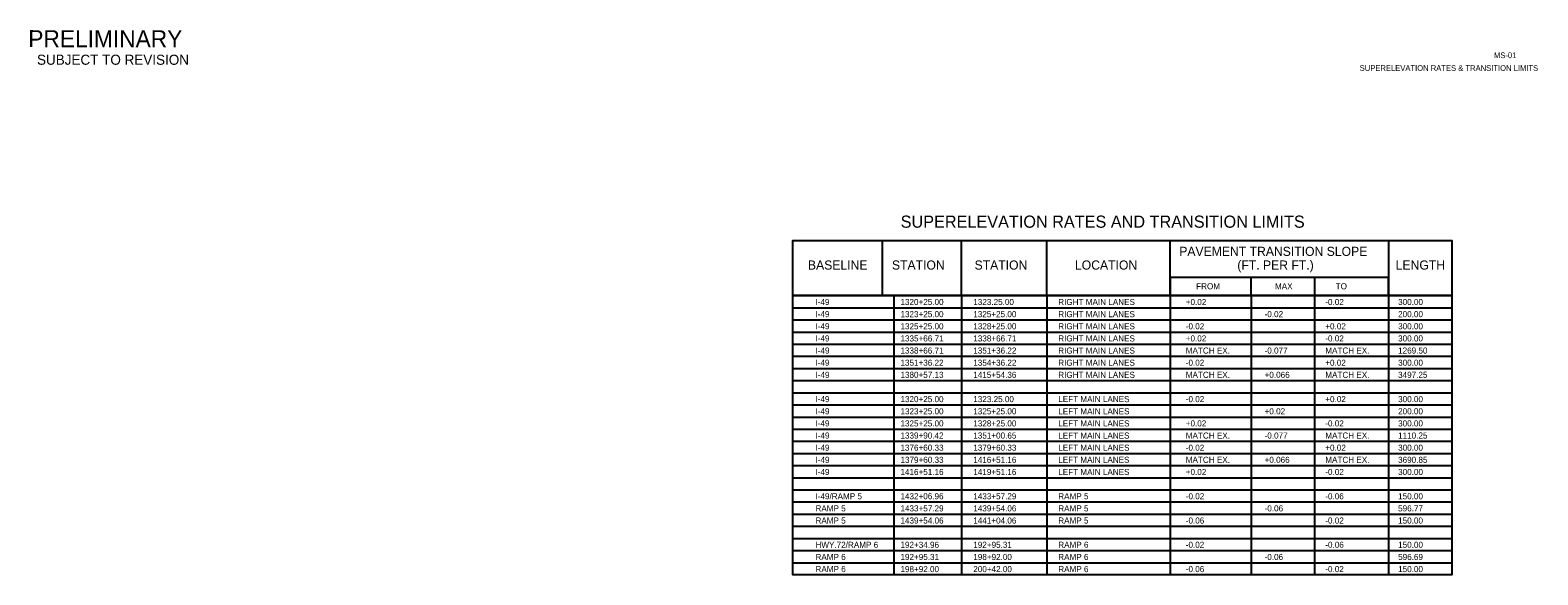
# Model space of a CAD drawing. Extents: x 1226579 to 1228132, y 151768 to 152328.
import ezdxf

# ---------------------------------------------------------------- set-up
doc = ezdxf.new("R2010")
doc.units = 0
for name, color, linetype in [('R_Border', 7, 'Continuous'), ('R_Border Notes', 7, 'Continuous'), ('R_Border Prem', 7, 'Continuous')]:
    doc.layers.add(name, color=color, linetype=linetype)

msp = doc.modelspace()

# ---------------------------------------------------------------- linework, layer by layer
at = {"layer": 'R_Border Notes'}
for p, q in [((1227456.8, 152055), (1227456.8, 152111.9)), ((1227538.1, 152055), (1227538.1, 152111.9)), ((1227625.9, 152055), (1227625.9, 152111.9)), ((1227753.1, 152055), (1227753.1, 152111.9)), ((1227977.8, 152111.9), (1227977.8, 151767.5)), ((1227836.6, 152055), (1227836.6, 152073.6)), ((1227901.8, 152073.6), (1227901.8, 151767.5)), ((1227387.8, 152055), (1228043, 152055)), ((1227468.5, 152055), (1227468.5, 151767.5)), ((1227538.1, 152055), (1227538.1, 151767.5)), ((1227625.9, 152055), (1227625.9, 151767.5)), ((1227753.1, 152055), (1227753.1, 151767.5)), ((1227836.6, 152055), (1227836.6, 151767.5)), ((1227364.5, 152042.5), (1228043, 152042.5)), ((1227364.5, 152030), (1228043, 152030)), ((1227364.5, 152017.5), (1228043, 152017.5)), ((1227364.5, 152005), (1228043, 152005)), ((1227364.5, 151992.5), (1228043, 151992.5)), ((1227364.5, 151980), (1228043, 151980)), ((1227364.5, 151967.5), (1228043, 151967.5)), ((1227364.5, 151955), (1228043, 151955)), ((1227364.5, 151942.5), (1228043, 151942.5)), ((1227364.5, 151930), (1228043, 151930)), ((1227364.5, 151917.5), (1228043, 151917.5)), ((1227364.5, 151905), (1228043, 151905)), ((1227364.5, 151892.5), (1228043, 151892.5)), ((1227364.5, 151880), (1228043, 151880)), ((1227364.5, 151867.5), (1228043, 151867.5)), ((1227364.5, 151855), (1228043, 151855)), ((1227364.5, 151842.5), (1228043, 151842.5)), ((1227364.5, 151830), (1228043, 151830)), ((1227364.5, 151817.5), (1228043, 151817.5)), ((1227364.5, 151805), (1228043, 151805)), ((1227364.5, 151792.5), (1228043, 151792.5)), ((1227364.5, 151780), (1228043, 151780))]:
    msp.add_line(p, q, dxfattribs=at)
for points in [[(1228043, 152055), (1227364.5, 152055), (1227364.5, 152111.9), (1228043, 152111.9)], [(1227753.1, 152055), (1227977.8, 152055), (1227977.8, 152073.6), (1227753.1, 152073.6)], [(1227364.5, 152055), (1228043, 152055), (1228043, 151767.5), (1227364.5, 151767.5)]]:
    msp.add_lwpolyline(points, close=True, dxfattribs=at)

# ---------------------------------------------------------------- texts
at = {"layer": 'R_Border'}
for s, height, p in [('MS-01', 5.86, (1228086.5, 152299.5)), ('SUPERELEVATION RATES & TRANSITION LIMITS', 5.862, (1227948.2, 152286.4))]:
    msp.add_text(s, height=height, dxfattribs=at).set_placement(p)
at = {"layer": 'R_Border Notes'}
for s, height, p in [('SUPERELEVATION RATES AND TRANSITION LIMITS', 12.5, (1227475.5, 152124.9)), ('PAVEMENT TRANSITION SLOPE', 9.375, (1227762.4, 152095.9)), ('BASELINE', 9.38, (1227380, 152081.8)), ('STATION', 9.38, (1227466.5, 152081.8)), ('STATION', 9.38, (1227551.6, 152081.8)), ('LOCATION', 9.38, (1227655, 152081.8)), ('(FT. PER FT.)', 9.375, (1227822.2, 152081.8)), ('LENGTH', 9.38, (1227985.3, 152081.8)), ('FROM', 6.25, (1227779.8, 152061.5)), ('MAX', 6.25, (1227861, 152061.5)), ('TO', 6.25, (1227923.5, 152061.5)), ('I-49', 6.25, (1227387.8, 152045.3)), ('I-49', 6.25, (1227387.8, 152032.8)), ('1320+25.00', 6.25, (1227475.3, 152045.3)), ('1323+25.00', 6.25, (1227475.3, 152032.8)), ('1323.25.00', 6.25, (1227550.3, 152045.3)), ('1325+25.00', 6.25, (1227550.3, 152032.8)), ('RIGHT MAIN LANES', 6.25, (1227637.8, 152045.3)), ('RIGHT MAIN LANES', 6.25, (1227637.8, 152032.8)), ('+0.02', 6.25, (1227769.1, 152045.3)), ('-0.02', 6.25, (1227850.3, 152032.8)), ('-0.02', 6.25, (1227912.8, 152045.3)), ('300.00', 6.25, (1227987.8, 152045.3)), ('200.00', 6.25, (1227987.8, 152032.8)), ('I-49', 6.25, (1227387.8, 152020.3)), ('1325+25.00', 6.25, (1227475.3, 152020.3)), ('1328+25.00', 6.25, (1227550.3, 152020.3)), ('RIGHT MAIN LANES', 6.25, (1227637.8, 152020.3)), ('-0.02', 6.25, (1227769.1, 152020.3)), ('+0.02', 6.25, (1227912.8, 152020.3)), ('300.00', 6.25, (1227987.8, 152020.3)), ('I-49', 6.25, (1227387.8, 152007.8)), ('1335+66.71', 6.25, (1227475.3, 152007.8)), ('1338+66.71', 6.25, (1227550.3, 152007.8)), ('RIGHT MAIN LANES', 6.25, (1227637.8, 152007.8)), ('+0.02', 6.25, (1227769.1, 152007.8)), ('-0.02', 6.25, (1227912.8, 152007.8)), ('300.00', 6.25, (1227987.8, 152007.8)), ('I-49', 6.25, (1227387.8, 151995.3)), ('1338+66.71', 6.25, (1227475.3, 151995.3)), ('1351+36.22', 6.25, (1227550.3, 151995.3)), ('RIGHT MAIN LANES', 6.25, (1227637.8, 151995.3)), ('MATCH EX.', 6.25, (1227769.1, 151995.3)), ('-0.077', 6.25, (1227850.3, 151995.3)), ('MATCH EX.', 6.25, (1227912.8, 151995.3)), ('1269.50', 6.25, (1227987.8, 151995.3)), ('I-49', 6.25, (1227387.8, 151982.8)), ('I-49', 6.25, (1227387.8, 151970.3)), ('1351+36.22', 6.25, (1227475.3, 151982.8)), ('1380+57.13', 6.25, (1227475.3, 151970.3)), ('1354+36.22', 6.25, (1227550.3, 151982.8)), ('1415+54.36', 6.25, (1227550.3, 151970.3)), ('RIGHT MAIN LANES', 6.25, (1227637.8, 151982.8)), ('RIGHT MAIN LANES', 6.25, (1227637.8, 151970.3)), ('-0.02', 6.25, (1227769.1, 151982.8)), ('MATCH EX.', 6.25, (1227769.1, 151970.3)), ('+0.066', 6.25, (1227850.3, 151970.3)), ('+0.02', 6.25, (1227912.8, 151982.8)), ('MATCH EX.', 6.25, (1227912.8, 151970.3)), ('300.00', 6.25, (1227987.8, 151982.8)), ('3497.25', 6.25, (1227987.8, 151970.3)), ('I-49', 6.25, (1227387.8, 151945.3)), ('1320+25.00', 6.25, (1227475.3, 151945.3)), ('1323.25.00', 6.25, (1227550.3, 151945.3)), ('LEFT MAIN LANES', 6.25, (1227637.8, 151945.3)), ('-0.02', 6.25, (1227769.1, 151945.3)), ('+0.02', 6.25, (1227912.8, 151945.3)), ('300.00', 6.25, (1227987.8, 151945.3)), ('I-49', 6.25, (1227387.8, 151932.8)), ('1323+25.00', 6.25, (1227475.3, 151932.8)), ('1325+25.00', 6.25, (1227550.3, 151932.8)), ('LEFT MAIN LANES', 6.25, (1227637.8, 151932.8)), ('+0.02', 6.25, (1227850.3, 151932.8)), ('200.00', 6.25, (1227987.8, 151932.8)), ('I-49', 6.25, (1227387.8, 151920.3)), ('I-49', 6.25, (1227387.8, 151907.8)), ('1325+25.00', 6.25, (1227475.3, 151920.3)), ('1339+90.42', 6.25, (1227475.3, 151907.8)), ('1328+25.00', 6.25, (1227550.3, 151920.3)), ('1351+00.65', 6.25, (1227550.3, 151907.8)), ('LEFT MAIN LANES', 6.25, (1227637.8, 151920.3)), ('LEFT MAIN LANES', 6.25, (1227637.8, 151907.8)), ('+0.02', 6.25, (1227769.1, 151920.3)), ('MATCH EX.', 6.25, (1227769.1, 151907.8)), ('-0.077', 6.25, (1227850.3, 151907.8)), ('-0.02', 6.25, (1227912.8, 151920.3)), ('MATCH EX.', 6.25, (1227912.8, 151907.8)), ('300.00', 6.25, (1227987.8, 151920.3)), ('1110.25', 6.25, (1227987.8, 151907.8)), ('I-49', 6.25, (1227387.8, 151895.3)), ('1376+60.33', 6.25, (1227475.3, 151895.3)), ('1379+60.33', 6.25, (1227550.3, 151895.3)), ('LEFT MAIN LANES', 6.25, (1227637.8, 151895.3)), ('-0.02', 6.25, (1227769.1, 151895.3)), ('+0.02', 6.25, (1227912.8, 151895.3)), ('300.00', 6.25, (1227987.8, 151895.3)), ('I-49', 6.25, (1227387.8, 151882.8)), ('1379+60.33', 6.25, (1227475.3, 151882.8)), ('1416+51.16', 6.25, (1227550.3, 151882.8)), ('LEFT MAIN LANES', 6.25, (1227637.8, 151882.8)), ('MATCH EX.', 6.25, (1227769.1, 151882.8)), ('+0.066', 6.25, (1227850.3, 151882.8)), ('MATCH EX.', 6.25, (1227912.8, 151882.8)), ('3690.85', 6.25, (1227987.8, 151882.8)), ('I-49', 6.25, (1227387.8, 151870.3)), ('1416+51.16', 6.25, (1227475.3, 151870.3)), ('1419+51.16', 6.25, (1227550.3, 151870.3)), ('LEFT MAIN LANES', 6.25, (1227637.8, 151870.3)), ('+0.02', 6.25, (1227769.1, 151870.3)), ('-0.02', 6.25, (1227912.8, 151870.3)), ('300.00', 6.25, (1227987.8, 151870.3)), ('I-49/RAMP 5', 6.25, (1227387.8, 151845.3)), ('1432+06.96', 6.25, (1227475.3, 151845.3)), ('1433+57.29', 6.25, (1227550.3, 151845.3)), ('RAMP 5', 6.25, (1227637.8, 151845.3)), ('-0.02', 6.25, (1227769.1, 151845.3)), ('-0.06', 6.25, (1227912.8, 151845.3)), ('150.00', 6.25, (1227987.8, 151845.3)), ('RAMP 5', 6.25, (1227387.8, 151832.8)), ('1433+57.29', 6.25, (1227475.3, 151832.8)), ('1439+54.06', 6.25, (1227550.3, 151832.8)), ('RAMP 5', 6.25, (1227637.8, 151832.8)), ('-0.06', 6.25, (1227850.3, 151832.8)), ('596.77', 6.25, (1227987.8, 151832.8)), ('RAMP 5', 6.25, (1227387.8, 151820.3)), ('1439+54.06', 6.25, (1227475.3, 151820.3)), ('1441+04.06', 6.25, (1227550.3, 151820.3)), ('RAMP 5', 6.25, (1227637.8, 151820.3)), ('-0.06', 6.25, (1227769.1, 151820.3)), ('-0.02', 6.25, (1227912.8, 151820.3)), ('150.00', 6.25, (1227987.8, 151820.3)), ('HWY.72/RAMP 6', 6.25, (1227387.8, 151795.3)), ('RAMP 6', 6.25, (1227387.8, 151782.8)), ('192+34.96', 6.25, (1227475.3, 151795.3)), ('192+95.31', 6.25, (1227475.3, 151782.8)), ('192+95.31', 6.25, (1227550.3, 151795.3)), ('198+92.00', 6.25, (1227550.3, 151782.8)), ('RAMP 6', 6.25, (1227637.8, 151795.3)), ('RAMP 6', 6.25, (1227637.8, 151782.8)), ('-0.02', 6.25, (1227769.1, 151795.3)), ('-0.06', 6.25, (1227850.3, 151782.8)), ('-0.06', 6.25, (1227912.8, 151795.3)), ('596.69', 6.25, (1227987.8, 151782.8)), ('150.00', 6.25, (1227987.8, 151795.3)), ('RAMP 6', 6.25, (1227387.8, 151770.3)), ('198+92.00', 6.25, (1227475.3, 151770.3)), ('200+42.00', 6.25, (1227550.3, 151770.3)), ('RAMP 6', 6.25, (1227637.8, 151770.3)), ('-0.06', 6.25, (1227769.1, 151770.3)), ('-0.02', 6.25, (1227912.8, 151770.3)), ('150.00', 6.25, (1227987.8, 151770.3))]:
    msp.add_text(s, height=height, dxfattribs=at).set_placement(p)
at = {"layer": 'R_Border Prem'}
for s, height, p in [('PRELIMINARY', 17.5, (1226577.1, 152310.8)), ('SUBJECT TO REVISION', 10.376, (1226586.1, 152292.7))]:
    msp.add_text(s, height=height, rotation=359.975, dxfattribs=at).set_placement(p)

doc.saveas('drawing.dxf')
